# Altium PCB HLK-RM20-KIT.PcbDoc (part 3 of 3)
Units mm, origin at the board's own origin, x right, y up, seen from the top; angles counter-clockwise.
Board outline 152 x 109 mm, 2 copper layers (Top Layer, Bottom Layer), stack 0.325 mm thick; 212 components, 285 nets, 988 pads, 747 vias.
Unrouted connection lines stored in the file: 195.
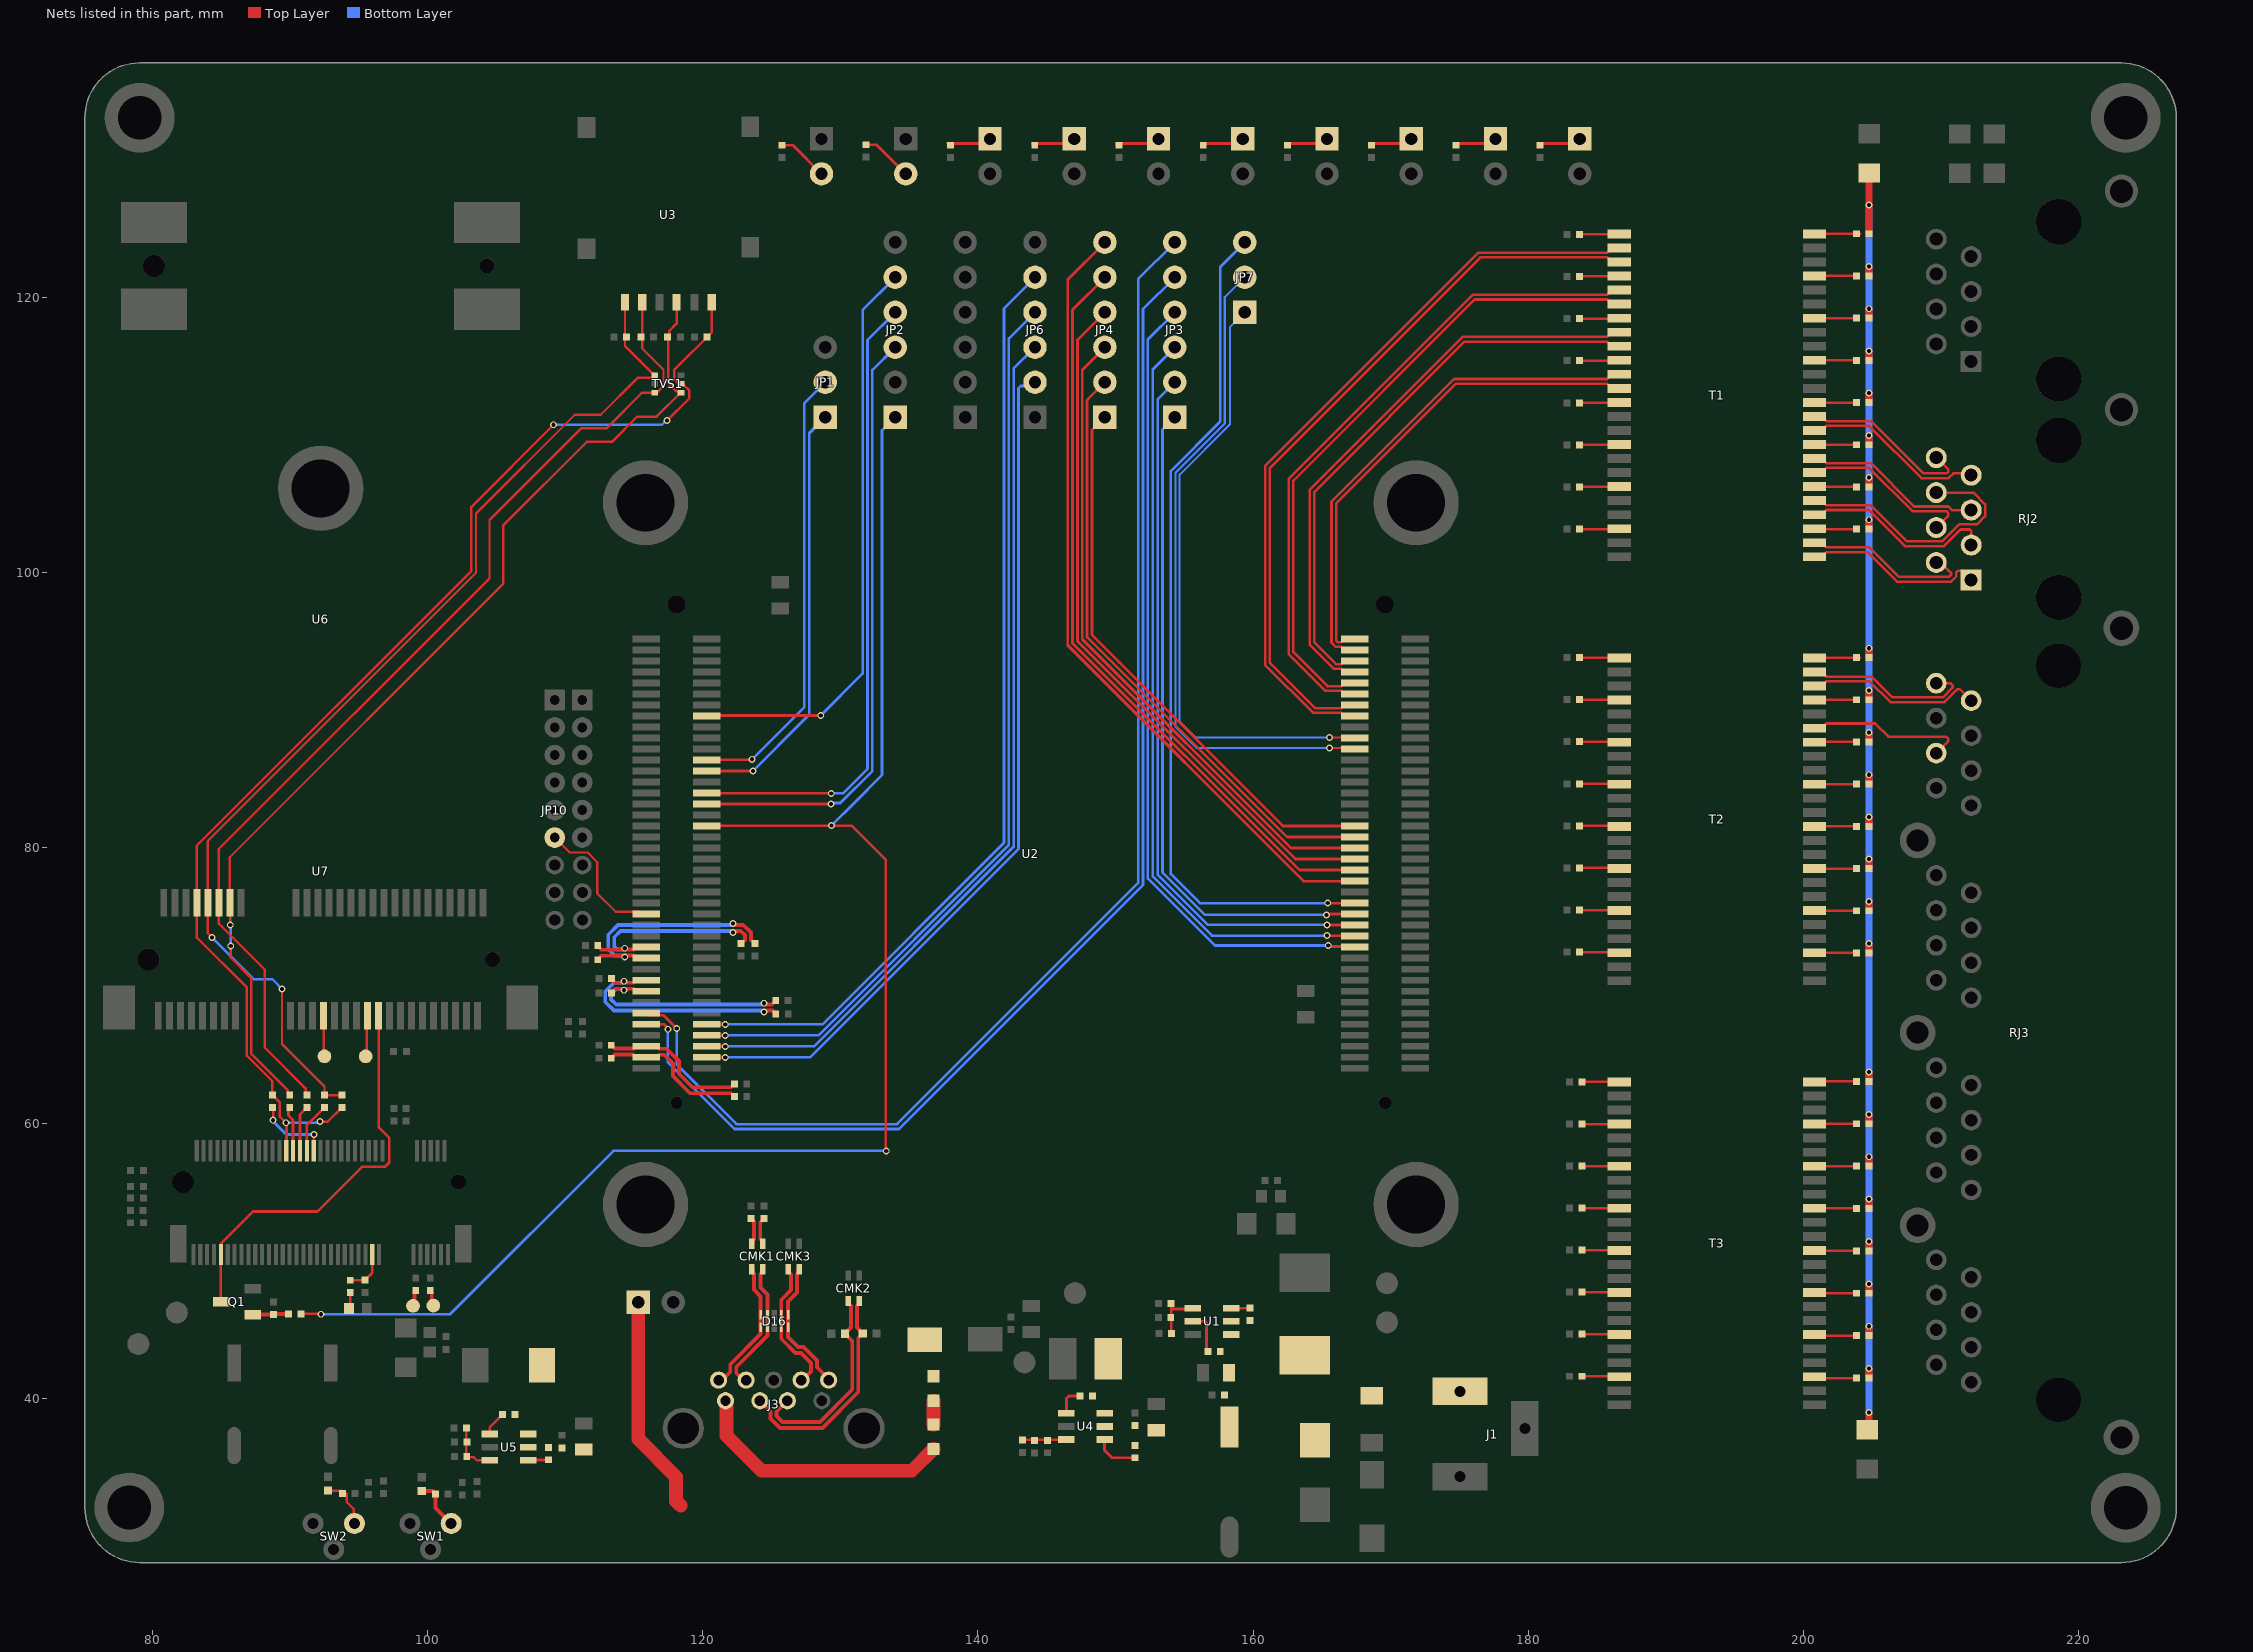
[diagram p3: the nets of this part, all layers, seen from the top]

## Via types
v1: diameter 0.5, hole 0.3, Top Layer to Bottom Layer, tented both sides, 747 vias

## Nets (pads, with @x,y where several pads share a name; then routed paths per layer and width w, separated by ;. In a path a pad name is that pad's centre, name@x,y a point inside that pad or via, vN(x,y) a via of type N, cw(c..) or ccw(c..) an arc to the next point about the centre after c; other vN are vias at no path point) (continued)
MTXV_P4_C_P: RJ3.D4 T2.43 | length 11.7
  Top Layer w0.188: T2.43@200.794,88.7 201.324,88.7 201.55,88.926 201.55,88.93 201.66,89.04 205.204,89.04 206.154,88.09 210.364,88.09 210.526,87.929 210.526,87.773 RJ3.D4@209.64,86.887
MTXV_P4_D_N: RJ3.D8 T2.47 | length 12.5
  Top Layer w0.188: T2.47@200.794,92.78 201.324,92.78 201.55,92.554 201.55,92.551 201.66,92.441 204.938,92.441 206.444,90.935 210.116,90.935 210.829,91.648 210.829,91.804 210.665,91.967 RJ3.D8@209.64,91.967
MTXV_P4_D_P: RJ3.D7 T2.46 | length 12.9
  Top Layer w0.188: T2.46@200.794,91.76 201.324,91.76 201.55,91.986 201.55,91.99 201.66,92.1 204.797,92.1 206.303,90.595 210.257,90.595 211.192,91.529 211.348,91.529 RJ3.D7@212.18,90.697
MTXV_P5_A_N: RJ2.2 T1.26 | length 12.5
  Top Layer w0.188: T1.26@200.794,102.175 201.324,102.175 201.55,101.949 201.55,101.946 201.66,101.836 204.785,101.836 206.927,99.693 210.577,99.693 210.712,99.829 210.712,99.984 209.959,100.737 RJ2.2@209.64,100.737
MTXV_P5_A_P: RJ2.1 T1.25 | length 13.2
  Top Layer w0.188: T1.25@200.794,101.155 201.324,101.155 201.55,101.381 201.55,101.385 201.66,101.495 204.644,101.495 206.786,99.353 210.718,99.353 211.094,99.728 211.094,100.025 211.204,100.135 211.512,100.135 RJ2.1@212.18,99.467
MTXV_P5_B_N: RJ2.6 T1.29 | length 19.1
  Top Layer w0.188: T1.29@200.794,105.235 201.324,105.235 201.55,105.009 201.55,105.006 201.66,104.896 204.886,104.896 207.513,102.269 210.057,102.269 211.306,103.517 212.593,103.517 213.188,104.113 213.188,104.965 212.336,105.817 RJ2.6@209.64,105.817
MTXV_P5_B_P: RJ2.3 T1.28 | length 14.2
  Top Layer w0.188: T1.28@200.794,104.215 201.324,104.215 201.55,104.441 201.55,104.445 201.66,104.555 204.745,104.555 207.372,101.929 210.198,101.929 211.409,103.139 212.07,103.139 212.18,103.029 RJ2.3@212.18,102.007
MTXV_P5_C_N: RJ2.5 T1.32 | length 12.9
  Top Layer w0.188: T1.32@200.794,108.295 201.324,108.295 201.55,108.069 201.55,108.066 201.66,107.956 204.893,107.956 208.04,104.809 210.517,104.809 210.778,104.547 RJ2.5@212.18,104.547
MTXV_P5_C_P: RJ2.4 T1.31 | length 12.6
  Top Layer w0.188: T1.31@200.794,107.275 201.324,107.275 201.55,107.501 201.55,107.505 201.66,107.615 204.752,107.615 207.899,104.469 210.376,104.469 210.526,104.319 210.526,104.163 RJ2.4@209.64,103.277
MTXV_P5_D_N: RJ2.8 T1.35 | length 12.9
  Top Layer w0.188: T1.35@200.794,111.355 201.324,111.355 201.55,111.129 201.55,111.126 201.66,111.016 204.9,111.016 208.698,107.218 210.403,107.218 210.514,107.328 210.514,107.484 RJ2.8@209.64,108.357
MTXV_P5_D_P: RJ2.7 T1.34 | length 13.3
  Top Layer w0.188: T1.34@200.794,110.335 201.324,110.335 201.55,110.561 201.55,110.565 201.66,110.675 204.759,110.675 208.557,106.877 210.544,106.877 210.89,107.223 212.044,107.223 RJ2.7@212.18,107.087
NetC1_1: C1.1 U1.6 | length 1.3
  Top Layer w0.188: U1.6@158.422,46.543 158.43,46.55 159.743,46.55 C1.1@159.751,46.558
NetC1_2: C1.2 L1.1 U1.5
NetC7_1: C7.1 U5.1 | length 1.8
  Top Layer w0.178: U5.1@104.53,37.393 104.53,37.904 C7.1@105.442,38.816
NetC7_2: C7.2 L2.1 U5.6
NetC8_1: C8.1 R2.2 R5.1 U1.1 | length 3.8
  Top Layer w0.2: C8.1@154.043,46.888 154.046,46.886 154.046,46.488 ; R5.1@154.049,44.706 154.046,44.709 154.046,46.488 ; U1.1@155.622,46.543 155.567,46.488 154.046,46.488
NetC15_1: C15.1 U4.1 | length 2.1
  Top Layer w0.2: U4.1@146.429,38.91 146.429,39.997 146.602,40.17 C15.1@147.4,40.17
NetC15_2: C15.2 L4.1 U4.6
NetC20_1: C20.1 R6.2 R7.1 U5.3 | length 3.9
  Top Layer w0.178: R7.1@102.818,35.781 R6.2@102.818,37.85 ; R7.1@102.845,35.781 102.919,35.708 103.362,35.708 103.576,35.493 U5.3@104.53,35.493
NetC23_1: C23.1 R10.2 R12.1 U4.3 | length 3.2
  Top Layer w0.2: C23.1@143.23,36.961 143.255,36.985 146.405,36.985 U4.3@146.429,37.01
NetC32_1: C32.1 CMK1.2 | length 2
  Top Layer w0.283: C32.1@123.501,53.072 123.713,52.86 123.713,51.574 123.6,51.462 123.6,51.287 CMK1.2@123.541,51.229
NetC33_1: C33.1 CMK1.1 | length 2
  Top Layer w0.283: CMK1.1@124.341,51.229 124.341,51.404 124.174,51.57 124.174,52.788 C33.1@124.458,53.072
NetC34_1: C34.1 C60.1 R38.1 R39.1 R40.1 R41.1 R42.1 R43.1 R45.1 R46.1 R47.1 R48.1 R49.1 R50.1 R51.1 R52.1 R53.1 R54.1 R55.1 R56.1 R57.1 R58.1 R59.1 R60.1 R61.1 R62.1 | length 109.1
  Top Layer w0.5: C60.1@204.62,37.712 204.747,37.839 v1(204.747,38.953) ; R38.1@204.747,124.68 v1(204.747,126.71) 204.747,129.019 C34.1@204.772,129.044 ; R62.1@204.751,41.472 v1@204.751,42.156 ; R61.1@204.751,44.552 v1@204.751,45.235 ; R60.1@204.751,47.632 v1@204.751,48.315 ; R59.1@204.751,50.712 v1@204.751,51.395 ; R58.1@204.751,53.792 v1@204.751,54.475 ; R57.1@204.751,56.872 v1@204.751,57.555 ; R56.1@204.751,59.952 v1@204.751,60.635 ; R55.1@204.751,63.032 v1@204.751,63.715 ; R54.1@204.751,72.369 v1@204.751,73.052 ; R53.1@204.751,75.435 v1@204.751,76.118 ; R52.1@204.751,78.5 v1@204.751,79.183 ; R51.1@204.751,81.565 v1@204.751,82.249 ; R50.1@204.751,84.631 v1@204.751,85.314 ; R49.1@204.751,87.696 v1@204.751,88.38 ; R48.1@204.751,90.762 v1@204.751,91.445 ; R47.1@204.751,93.827 v1@204.751,94.51 ; R46.1@204.751,103.165 v1@204.751,103.848 ; R45.1@204.751,106.232 v1@204.751,106.915 ; R43.1@204.751,109.299 v1@204.751,109.982 ; R42.1@204.751,112.366 v1@204.751,113.049 ; R41.1@204.751,115.432 v1@204.751,116.116 ; R40.1@204.751,118.499 v1@204.751,119.183 ; R39.1@204.751,121.566 v1@204.751,122.249
  Bottom Layer w0.5: v1(204.747,38.953) v1(204.747,42.154) 204.751,42.157 204.751,48.314 204.751,60.633 204.751,73.05 204.751,79.181 204.751,91.443 204.751,116.114 204.751,119.181 204.751,126.706 v1(204.747,126.71)
  other v1: 204.747,45.234 204.747,48.314 204.747,51.394 204.747,54.473 204.747,57.553 204.747,60.633 204.747,63.713 204.747,73.05 204.747,76.116 204.747,79.181 204.747,82.247 204.747,85.312 204.747,88.378 204.747,91.443 204.747,94.509 204.747,103.846 204.747,106.913 204.747,109.98 204.747,113.047 204.747,116.114 204.747,119.181 204.747,122.248
NetC35_2: C35.2 T1.1 | length 2.9
  Top Layer w0.181: C35.2@183.716,124.588 T1.1@186.566,124.588
NetC36_2: C36.2 T1.4 | length 2.9
  Top Layer w0.181: C36.2@183.716,121.528 186.566,121.528 T1.4@186.594,121.555
NetC37_2: C37.2 T1.7 | length 2.9
  Top Layer w0.181: C37.2@183.716,118.468 186.567,118.468 T1.7@186.594,118.495
NetC38_2: C38.2 T1.10 | length 2.9
  Top Layer w0.181: C38.2@183.716,115.408 186.567,115.408 T1.10@186.594,115.435
NetC39_2: C39.2 T1.13 | length 2.9
  Top Layer w0.181: C39.2@183.716,112.348 186.567,112.348 T1.13@186.594,112.375
NetC41_2: C41.2 T1.16 | length 2.9
  Top Layer w0.181: C41.2@183.716,109.288 186.567,109.288 T1.16@186.594,109.315
NetC42_2: C42.2 T1.19 | length 2.9
  Top Layer w0.181: C42.2@183.716,106.229 186.567,106.229 T1.19@186.594,106.255
NetC43_2: C43.2 T1.22 | length 2.9
  Top Layer w0.181: C43.2@183.716,103.169 186.567,103.169 T1.22@186.594,103.195
NetC44_2: C44.2 T2.1 | length 2.9
  Top Layer w0.181: C44.2@183.716,93.831 186.563,93.831 T2.1@186.594,93.8
NetC45_2: C45.2 T2.4 | length 2.9
  Top Layer w0.181: C45.2@183.716,90.773 186.561,90.773 T2.4@186.594,90.74
NetC46_2: C46.2 T2.7 | length 2.9
  Top Layer w0.181: C46.2@183.716,87.715 186.56,87.715 T2.7@186.594,87.68
NetC47_2: C47.2 T2.10 | length 2.9
  Top Layer w0.181: C47.2@183.716,84.656 186.558,84.656 T2.10@186.594,84.62
NetC48_2: C48.2 T2.13 | length 2.9
  Top Layer w0.181: C48.2@183.716,81.598 186.556,81.598 T2.13@186.594,81.56
NetC49_2: C49.2 T2.16 | length 2.9
  Top Layer w0.181: C49.2@183.716,78.54 186.555,78.54 T2.16@186.594,78.5
NetC50_2: C50.2 T2.19 | length 2.9
  Top Layer w0.181: C50.2@183.716,75.481 186.553,75.481 T2.19@186.594,75.44
NetC51_2: C51.2 T2.22 | length 2.9
  Top Layer w0.181: C51.2@183.716,72.423 186.551,72.423 T2.22@186.594,72.38
NetC52_2: C52.2 T3.1 | length 2.7
  Top Layer w0.181: C52.2@183.885,62.987 T3.1@186.594,62.985 T3.1@186.594,62.985
NetC53_2: C53.2 T3.4 | length 2.7
  Top Layer w0.181: C53.2@183.885,59.931 186.588,59.931 T3.4@186.594,59.925
NetC54_2: C54.2 T3.7 | length 2.7
  Top Layer w0.181: C54.2@183.885,56.876 186.583,56.876 T3.7@186.594,56.865
NetC55_2: C55.2 T3.10 | length 2.7
  Top Layer w0.181: C55.2@183.885,53.821 186.578,53.821 T3.10@186.594,53.805
NetC56_2: C56.2 T3.13 | length 2.7
  Top Layer w0.181: C56.2@183.885,50.766 186.573,50.766 T3.13@186.594,50.745
NetC57_2: C57.2 T3.16 | length 2.7
  Top Layer w0.181: C57.2@183.885,47.711 186.569,47.711 T3.16@186.594,47.685
NetC58_2: C58.2 T3.19 | length 2.7
  Top Layer w0.181: C58.2@183.885,44.656 186.564,44.656 T3.19@186.594,44.625
NetC59_2: C59.2 T3.22 | length 2.7
  Top Layer w0.181: C59.2@183.885,41.601 186.559,41.601 T3.22@186.594,41.565
NetCMK1_3: CMK1.3 D16.5 D16.6 J3.9 | length 9.8
  Top Layer w0.283: J3.9@121.148,41.32 121.41,41.32 121.993,41.903 121.993,42.454 124.203,44.664 D16.6@124.203,45.163 D16.5@124.203,46.063 124.203,47.411 123.709,47.905 123.709,49.035 123.6,49.145 123.6,49.32 CMK1.3@123.541,49.378
NetCMK1_4: CMK1.4 D16.4 D16.7 J3.8 | length 9.7
  Top Layer w0.283: J3.8@123.148,41.32 122.96,41.32 122.429,41.851 122.429,42.274 124.703,44.548 D16.7@124.703,45.163 D16.4@124.703,46.063 124.703,47.527 124.187,48.043 124.187,49.05 124.341,49.204 CMK1.4@124.341,49.378
NetCMK2_1: CMK2.1 D17.2 J3.3 | length 15
  Top Layer w0.283: J3.3@126.148,39.82 125.349,39.02 125.349,38.722 125.791,38.28 128.514,38.28 130.864,40.63 130.864,44.157 D17.2@130.326,44.695 130.761,45.13 130.761,46.693 130.621,46.834 130.621,47.009 CMK2.1@130.563,47.067
NetCMK2_2: CMK2.2 D18.2 J3.2 | length 16.3
  Top Layer w0.283: J3.2@124.148,39.82 124.913,39.055 124.913,38.541 125.61,37.844 128.695,37.844 131.3,40.449 131.3,44.39 D18.2@131.619,44.709 131.197,45.131 131.197,46.727 131.362,46.892 CMK2.2@131.362,47.067
NetCMK3_3: CMK3.3 D16.2 D16.9 J3.6 | length 9.9
  Top Layer w0.283: CMK3.3@126.219,49.378 126.277,49.32 126.277,49.145 126.42,49.002 126.42,47.87 125.703,47.152 D16.2@125.703,46.063 D16.9@125.703,45.163 125.703,44.329 126.743,43.289 127.129,43.289 127.859,42.558 127.859,41.943 127.237,41.32 J3.6@127.148,41.32
NetCMK3_4: CMK3.4 D16.1 D16.10 J3.5 | length 9.8
  Top Layer w0.283: CMK3.4@127.019,49.378 126.96,49.32 126.96,49.145 126.856,49.041 126.856,47.689 126.203,47.036 D16.1@126.203,46.063 D16.10@126.203,45.163 126.203,44.445 126.924,43.725 127.309,43.725 128.295,42.739 128.295,42.252 129.148,41.399 J3.5@129.148,41.32
NetD4_1: D4.1 R13.1 | length 3
  Top Layer w0.2: R13.1@180.852,131.188 183.427,131.188 D4.1@183.729,131.489
NetD5_1: D5.1 R17.1 | length 3.2
  Top Layer w0.2: R17.1@174.699,131.188 177.501,131.188 D5.1@177.803,131.489
NetD6_1: D6.1 R20.1 | length 3.2
  Top Layer w0.2: R20.1@168.546,131.188 171.337,131.188 D6.1@171.638,131.489
NetD7_2: D7.2 R19.1 SW1.2 | length 3.7
  Top Layer w0.3: D7.2@99.569,33.259 100.37,33.259 R19.1@100.586,33.043 100.586,32.036 SW1.2@101.716,30.906
NetD8_1: D8.1 R23.1 | length 3.2
  Top Layer w0.2: R23.1@162.393,131.188 165.172,131.188 D8.1@165.473,131.489
NetD9_1: D9.1 R26.1 | length 3.1
  Top Layer w0.2: R26.1@156.24,131.188 158.939,131.188 D9.1@159.24,131.489
NetD10_1: D10.1 R31.1 | length 3.1
  Top Layer w0.2: R31.1@150.087,131.188 152.774,131.188 D10.1@153.076,131.489
NetD11_1: D11.1 R34.1 | length 3.1
  Top Layer w0.2: R34.1@143.934,131.188 146.61,131.188 D11.1@146.911,131.489
NetD12_2: D12.2 R30.1 SW2.2 | length 3.6
  Top Layer w0.178: D12.2@92.755,33.289 93.721,33.289 93.721,33.178 R30.1@93.825,33.074 ; 94.129,33.07 94.129,32.445 94.64,31.934 94.64,30.945 SW2.2@94.679,30.906
NetD13_1: D13.1 R35.1 | length 3.1
  Top Layer w0.2: R35.1@137.781,131.188 140.445,131.188 D13.1@140.747,131.489
NetD14_2: D14.2 R8.1 | length 3.7
  Top Layer w0.2: R8.1@125.759,131.063 126.544,131.063 D14.2@128.626,128.981
NetD19_2: D19.2 R27.1 | length 1.2
  Top Layer w0.2: D19.2@94.284,46.517 94.382,46.615 R27.1@94.382,47.673
NetD20_2: D20.2 R32.2 | length 3.8
  Top Layer w0.2: R32.2@131.873,131.101 132.628,131.101 D20.2@134.748,128.981
NetF1_1: F1.1 J3.1 | length 19.3
  Top Layer w1: J3.1@121.648,39.82 121.696,39.772 121.696,39.595 121.722,39.569 121.722,37.278 124.265,34.735 135.185,34.735 F1.1@136.772,36.322
NetF1_2: F1.2 FB1.2 | length 1.7
  Top Layer w1: F1.2@136.772,38.1 FB1.2@136.772,39.827
NetF2_1: F2.1 J1.1
NetQ1_1: Q1.1 R11.1 R14.2 | length 2.6
  Top Layer w0.283: Q1.1@87.277,46.067 87.287,46.077 88.798,46.077 R14.2@88.808,46.087 88.832,46.111 89.864,46.111 R11.1@89.888,46.134
NetR1_2: R1.2 U1.2 | length 3.1
  Top Layer w0.188: U1.2@155.622,45.593 156.495,45.593 156.605,45.483 R1.2@156.605,43.383
NetR4_2: R4.2 U5.4 | length 1.5
  Top Layer w0.2: U5.4@107.33,35.493 107.348,35.511 108.757,35.511 R4.2@108.775,35.529
NetR9_2: R9.2 U4.4 | length 3.2
  Top Layer w0.2: U4.4@149.229,37.01 149.191,36.972 149.191,36.221 149.733,35.679 R9.2@151.407,35.679
NetR21_2: R21.2 U7.46 | length 3
  Top Layer w0.2: R21.2@89.897,61.134 89.897,60.549 90.225,60.221 U7.46@90.225,58.229
NetR22_2: R22.2 U7.44 | length 3.3
  Top Layer w0.2: U7.44@90.725,58 90.725,60.614 R22.2@91.244,61.134
NetR24_2: R24.2 U7.42 | length 5.5
  Top Layer w0.2: 92.021,60.65 91.225,59.853 ; 92.022,60.65 R24.2@92.506,61.134 ; 91.225,59.853 U7.42@91.225,58 91.225,59.853
NetR33_1: R33.1 TP3.1 | length 1.2
  Top Layer w0.283: TP3.1@98.944,46.716 99.041,46.813 99.041,47.733 R33.1@99.138,47.83
NetR37_1: R37.1 TP5.1 | length 1.2
  Top Layer w0.283: R37.1@100.196,47.83 100.304,47.721 100.304,46.85 TP5.1@100.418,46.737
NetR38_2: R38.2 T1.48 | length 3.3
  Top Layer w0.181: T1.48@200.794,124.615 204.098,124.615 204.12,124.637
NetR39_2: R39.2 T1.45 | length 3.1
  Top Layer w0.181: T1.45@200.794,121.555 200.805,121.566 R39.2@203.851,121.566
NetR40_2: R40.2 T1.42 | length 3.1
  Top Layer w0.181: T1.42@200.794,118.495 200.798,118.499 R40.2@203.851,118.499
NetR41_2: R41.2 T1.39 | length 3.1
  Top Layer w0.181: T1.39@200.794,115.435 200.797,115.432 R41.2@203.851,115.432
NetR42_2: R42.2 T1.36 | length 3.1
  Top Layer w0.181: T1.36@200.794,112.375 200.804,112.366 R42.2@203.851,112.366
NetR43_2: R43.2 T1.33 | length 3.1
  Top Layer w0.181: T1.33@200.794,109.315 200.811,109.299 R43.2@203.851,109.299
NetR45_2: R45.2 T1.30 | length 3.1
  Top Layer w0.181: T1.30@200.794,106.255 200.818,106.232 R45.2@203.851,106.232
NetR46_2: R46.2 T1.27 | length 3.1
  Top Layer w0.181: T1.27@200.794,103.195 200.825,103.165 R46.2@203.851,103.165
NetR47_2: R47.2 T2.48 | length 3.3
  Top Layer w0.181: T2.48@200.794,93.8 200.821,93.827 203.824,93.827 203.851,93.8 R47.2@204.098,93.8
NetR48_2: R48.2 T2.45 | length 3.1
  Top Layer w0.181: T2.45@200.794,90.74 200.815,90.762 R48.2@203.851,90.762
NetR49_2: R49.2 T2.42 | length 3.1
  Top Layer w0.181: T2.42@200.794,87.68 200.81,87.696 203.839,87.696 R49.2@203.851,87.684
NetR50_2: R50.2 T2.39 | length 3.1
  Top Layer w0.181: T2.39@200.794,84.62 200.805,84.631 R50.2@203.851,84.631
NetR51_2: R51.2 T2.36 | length 3.1
  Top Layer w0.181: T2.36@200.794,81.56 200.799,81.565 203.836,81.565 R51.2@203.851,81.55
NetR52_2: R52.2 T2.33 | length 6.1
  Top Layer w0.181: T2.33@200.794,78.5 R52.2@203.851,78.5 ; T2.33@200.811,78.483 R52.2@203.851,78.483
NetR53_2: R53.2 T2.30 | length 3.1
  Top Layer w0.181: T2.30@200.794,75.44 200.8,75.435 203.833,75.435 R53.2@203.851,75.417
NetR54_2: R54.2 T2.27 | length 3.1
  Top Layer w0.181: T2.27@200.794,72.38 200.805,72.369 R54.2@203.851,72.369
NetR55_2: R55.2 T3.48 | length 3.1
  Top Layer w0.181: T3.48@200.794,62.985 200.841,63.032 R55.2@203.851,63.032
NetR56_2: R56.2 T3.45 | length 3.1
  Top Layer w0.181: T3.45@200.794,59.925 200.821,59.952 R56.2@203.851,59.952
NetR57_2: R57.2 T3.42 | length 3.1
  Top Layer w0.181: T3.42@200.794,56.865 200.801,56.872 R57.2@203.851,56.872
NetR58_2: R58.2 T3.39 | length 3.1
  Top Layer w0.181: T3.39@200.794,53.805 200.807,53.792 R58.2@203.851,53.792
NetR59_2: R59.2 T3.36 | length 3.1
  Top Layer w0.181: T3.36@200.794,50.745 200.827,50.712 R59.2@203.851,50.712
NetR60_2: R60.2 T3.33 | length 3.1
  Top Layer w0.181: T3.33@200.794,47.685 200.847,47.632 R60.2@203.851,47.632
NetR61_2: R61.2 T3.30 | length 3.1
  Top Layer w0.181: T3.30@200.794,44.625 200.867,44.552 R61.2@203.851,44.552
NetR62_2: R62.2 T3.27 | length 3.1
  Top Layer w0.181: T3.27@200.794,41.565 200.887,41.472 R62.2@203.851,41.472
P0_A_TXV_N: T1.11 U2.A77 | length 36.9
  Top Layer w0.188: U2.A77@167.386,94.383 166.636,94.383 166.406,94.613 165.999,94.613 165.689,94.922 165.689,105.17 174.594,114.076 185.728,114.076 185.838,114.186 185.838,114.189 186.064,114.415 T1.11@186.594,114.415
P0_A_TXV_P: T1.12 U2.A79 | length 35.8
  Top Layer w0.188: U2.A79@167.386,95.183 166.636,95.183 166.406,94.953 166.14,94.953 166.029,95.063 166.029,105.029 174.735,113.735 185.728,113.735 185.838,113.625 185.838,113.621 186.064,113.395 T1.12@186.594,113.395
P0_B_TXV_N: T1.8 U2.A73 | length 42.6
  Top Layer w0.188: U2.A73@167.386,92.783 166.636,92.783 166.406,93.013 165.876,93.013 164.099,94.79 164.099,106.008 175.227,117.136 185.728,117.136 185.838,117.246 185.838,117.249 186.064,117.475 T1.8@186.594,117.475
P0_B_TXV_P: T1.9 U2.A75 | length 41.4
  Top Layer w0.188: U2.A75@167.386,93.583 166.636,93.583 166.406,93.353 166.017,93.353 164.44,94.931 164.44,105.867 175.368,116.795 185.728,116.795 185.838,116.685 185.838,116.681 185.938,116.582 T1.9@186.609,116.582
P0_C_TXV_N: T1.5 U2.A69 | length 48.4
  Top Layer w0.188: U2.A69@167.386,91.183 166.636,91.183 166.406,91.413 165.255,91.413 162.575,94.093 162.575,106.821 175.95,120.196 185.728,120.196 185.838,120.306 185.838,120.309 186.064,120.535 T1.5@186.594,120.535
P0_C_TXV_P: T1.6 U2.A71 | length 47.3
  Top Layer w0.188: U2.A71@167.386,91.983 166.636,91.983 166.406,91.753 165.396,91.753 162.916,94.234 162.916,106.68 176.091,119.855 185.728,119.855 185.838,119.745 185.838,119.741 186.064,119.515 T1.6@186.594,119.515
P0_D_TXV_N: T1.2 U2.A65 | length 54.8
  Top Layer w0.188: U2.A65@167.386,89.583 166.636,89.583 166.406,89.813 164.366,89.813 160.873,93.306 160.873,107.761 176.368,123.256 185.728,123.256 185.838,123.366 185.838,123.369 186.064,123.595 T1.2@186.594,123.595
P0_D_TXV_P: T1.3 U2.A67 | length 53.7
  Top Layer w0.188: U2.A67@167.386,90.383 166.636,90.383 166.406,90.153 164.507,90.153 161.214,93.447 161.214,107.62 176.509,122.915 185.728,122.915 185.838,122.805 185.838,122.801 186.064,122.575 T1.3@186.594,122.575
PCIE_CK_N: JP3.5 U2.B9 | length 93.2
  Top Layer w0.2: U2.B9@115.886,67.183 117.186,67.183 117.403,66.966 117.403,66.875 v1(117.46,66.817)
  Bottom Layer w0.2: v1(117.46,66.817) 117.46,64.413 122.307,59.566 134.258,59.566 151.993,77.301 151.993,119.15 JP3.5@154.305,121.463
PCIE_CK_P: JP3.6 U2.B11 | length 95.5
  Top Layer w0.2: U2.B11@115.886,67.983 116.036,67.833 117.155,67.833 v1(118.11,66.878)
  Bottom Layer w0.2: v1(118.11,66.878) 118.11,64.262 122.453,59.919 134.112,59.919 151.64,77.447 151.64,121.338 JP3.6@154.305,124.003
PCIE_PERESET_N: JP10.6 U2.B29 | length 9.9
  Top Layer w0.16: JP10.6@109.241,80.75 110.333,79.657 111.639,79.657 112.336,78.96 112.336,76.691 113.674,75.353 115.341,75.353 U2.B29@115.511,75.183
PERST#: Q1.3 U6.33 U7.67 | length 29.9
  Top Layer w0.2: Q1.3@84.991,47.017 84.975,47.033 U7.67@84.975,50.45 85.025,50.5 85.025,51.282 87.312,53.569 91.986,53.569 95.237,56.82 96.888,56.82 97.218,57.15 97.218,58.903 96.456,59.665 96.456,67.769 U6.33@96.425,67.8
PERST_4G: JP2.1 R11.2 U2.B46 | length 114.3
  Top Layer w0.2: R11.2@90.788,46.134 92.223,46.134 v1(92.25,46.108) ; U2.B46@120.286,81.583 120.319,81.617 v1(129.353,81.617) 130.813,81.617 133.305,79.125 133.305,58.007 v1(133.329,57.983)
  Bottom Layer w0.2: v1(92.25,46.108) 101.632,46.108 113.507,57.983 v1(133.329,57.983) ; v1(129.353,81.617) 130.98,83.244 130.98,83.245 133.027,85.292 133.027,110.345 JP2.1@133.985,111.303
PWM0: JP2.5 U2.B66 | length 42.4
  Top Layer w0.2: U2.B66@120.286,89.583 120.322,89.619 v1(128.57,89.619)
  Bottom Layer w0.2: v1(128.57,89.619) 131.618,92.667 131.618,119.095 JP2.5@133.985,121.463
SIM2_CLK: C12.1 R22.1 TVS1.3 U3.4 U6.12 | length 75.9
  Top Layer w0.178: R22.1@91.244,62.034 91.135,62.143 91.135,62.518 88.176,65.477 88.176,71.139 84.825,74.49 U6.12@84.825,76 84.825,79.908 104.5,99.583 104.5,103.835 111.155,110.49 112.991,110.49 115.565,113.064 TVS1.3@116.508,113.064 ; U3.4@115.596,119.65 115.596,116.292 117.143,114.745 117.143,113.558 TVS1.3@116.604,113.018
SIM2_DATA: C13.1 R3.1 R24.1 TVS1.1 U3.3 U6.10 | length 79.2
  Top Layer w0.178: v1(84.34,73.482) 84.34,73.495 84.025,73.81 U6.10@84.025,76 84.025,80.498 103.517,99.99 103.517,104.292 110.698,111.473 112.584,111.473 115.267,114.155 116.249,114.155 TVS1.1@116.458,114.364 ; v1(89.42,69.748) 89.42,65.735 92.506,62.65 R24.1@92.506,62.034 R3.1@93.768,62.034 ; U3.3@114.346,119.65 114.346,117.145 114.346,116.476 TVS1.1@116.458,114.364 ; TVS1.1@116.508,114.364 TVS1.1@116.458,114.364
  Bottom Layer w0.178: v1(84.34,73.482) 87.363,70.46 88.709,70.46 v1(89.42,69.748)
SIM2_DET: R25.2 U7.40 | length 5.5
  Top Layer w0.2: v1(88.761,60.21) 88.786,60.234 R25.2@88.786,61.134 ; U7.40@91.729,58.004 91.729,59.164 v1(91.733,59.168)
  Bottom Layer w0.2: v1(88.761,60.21) 88.761,60.134 89.726,59.168 v1(91.733,59.168)
SIM2_RST: C11.1 R21.1 TVS1.4 U3.5 U6.14 | length 75.6
  Top Layer w0.178: v1(85.662,74.395) 85.662,75.963 U6.14@85.625,76 85.625,79.318 105.483,99.176 105.483,103.428 111.562,109.507 113.398,109.507 115.233,111.343 116.637,111.343 TVS1.4@118.358,113.064 ; v1(85.691,72.864) 85.691,72.02 87.193,70.518 87.193,65.031 89.826,62.399 89.826,62.19 R21.1@89.982,62.034 ; U3.5@118.096,119.65 118.096,118.096 117.561,117.561 117.561,117.233 117.474,117.145 117.474,113.801 118.1,113.175 118.247,113.175 TVS1.4@118.358,113.064 ; TVS1.4@118.408,113.064 TVS1.4@118.358,113.064
  Bottom Layer w0.178: v1(85.662,74.395) 85.691,74.365 v1(85.691,72.864)
SIM2_VDD: C27.2 R3.2 R25.1 TVS1.5 U3.6 U6.8 U7.48 | length 90.1
  Top Layer w0.178: v1(89.705,60.021) 89.262,60.463 89.262,61.492 R25.1@88.721,62.034 88.721,63.037 86.863,64.895 86.863,69.842 83.225,73.48 U6.8@83.225,76 83.225,80.165 103.187,100.127 103.187,104.777 v1(109.159,110.749) ; v1(92.19,60.108) 92.742,60.108 R3.2@93.768,61.134 ; v1(117.399,111.049) 119.024,112.674 119.024,113.239 118.612,113.651 118.329,113.651 117.917,114.064 117.917,114.728 120.646,117.458 U3.6@120.646,119.65
  Top Layer w0.2: v1(89.705,60.021) 89.738,59.987 U7.48@89.738,58.013
  Bottom Layer w0.178: v1(89.705,60.021) 92.103,60.021 v1(92.19,60.108) ; v1(109.159,110.749) 117.029,110.749 117.328,111.049 v1(117.399,111.049)
SMI_MDC: JP7.1 U2.A61 | length 44.9
  Top Layer w0.152: v1(165.532,88.011) 167.358,88.011 U2.A61@167.386,87.983
  Bottom Layer w0.152: JP7.1@159.385,118.923 158.301,117.839 158.301,110.771 154.65,107.12 154.65,89.179 155.819,88.011 v1(165.532,88.011)
SMI_MDIO: JP7.2 U2.A59 | length 48.5
  Top Layer w0.152: v1(165.532,87.249) 167.32,87.249 U2.A59@167.386,87.183
  Bottom Layer w0.152: JP7.2@159.385,121.463 157.936,120.013 157.936,110.836 154.346,107.246 154.346,88.798 155.895,87.249 v1(165.532,87.249)
SPI1_CLK: JP2.3 U2.B50 | length 44.5
  Top Layer w0.2: U2.B50@120.286,83.183 120.3,83.197 v1(129.325,83.197)
  Bottom Layer w0.2: v1(129.325,83.197) 129.382,83.254 129.992,83.254 132.322,85.584 132.322,114.72 JP2.3@133.985,116.383
SPI1_CS: JP2.4 U2.B52 | length 46.5
  Top Layer w0.2: U2.B52@120.286,83.983 120.322,83.947 120.338,83.963 v1(129.335,83.963)
  Bottom Layer w0.2: v1(129.335,83.963) 130.203,83.963 131.97,85.73 131.97,116.908 JP2.4@133.985,118.923
SPI2_CLK: JP4.5 U2.A37 | length 54.9
  Top Layer w0.2: JP4.5@149.225,121.463 146.872,119.11 146.872,94.873 163.362,78.383 U2.A37@167.386,78.383
SPI2_CS: JP4.1 U2.A45 | length 41.1
  Top Layer w0.2: JP4.1@149.225,111.303 148.282,110.36 148.282,95.479 150.279,93.482 150.279,93.459 162.155,81.583 U2.A45@167.386,81.583
SPI2_HOLD: JP4.3 U2.A41 | length 48
  Top Layer w0.2: JP4.3@149.225,116.383 147.577,114.735 147.577,95.164 162.758,79.983 U2.A41@167.386,79.983
SPI2_MISO: JP4.6 U2.A35 | length 58.4
  Top Layer w0.2: JP4.6@149.225,124.003 146.52,121.298 146.52,94.727 163.663,77.583 U2.A35@167.386,77.583
SPI2_MOSI: JP4.2 U2.A43 | length 44.5
  Top Layer w0.2: JP4.2@149.225,113.843 147.93,112.547 147.93,95.31 149.192,94.048 162.457,80.783 U2.A43@167.386,80.783
SPI2_WP: JP4.4 U2.A39 | length 51.5
  Top Layer w0.2: JP4.4@149.225,118.923 147.225,116.923 147.225,95.018 163.06,79.183 U2.A39@167.386,79.183
SS_RX_N: R64.2 R71.2 U2.B15 | length 16.6
  Top Layer w0.283: R64.2@113.351,69.466 113.46,69.574 113.46,69.597 113.626,69.762 114.4,69.762 114.403,69.766 114.954,69.766 115.136,69.583 U2.B15@115.886,69.583 ; v1(124.437,68.712) 124.496,68.712 124.604,68.603 124.994,68.603 125.196,68.805 125.196,68.806 R71.2@125.305,68.915
  Bottom Layer w0.283: v1(114.285,69.657) 114.226,69.657 114.117,69.766 113.728,69.766 113.342,69.38 113.342,68.974 113.713,68.603 124.27,68.603 124.378,68.712 v1(124.437,68.712)
SS_RX_P: R65.2 R70.2 U2.B17 | length 17.8
  Top Layer w0.283: R65.2@113.351,70.495 113.46,70.386 113.46,70.364 113.626,70.198 v1@114.219,70.198 ; v1@114.439,70.201 114.954,70.201 115.136,70.383 U2.B17@115.886,70.383 ; v1(124.437,68.059) 124.496,68.059 124.604,68.168 125.066,68.168 R70.2@125.306,67.928
  Bottom Layer w0.283: v1(114.285,70.309) 114.226,70.309 114.117,70.201 113.547,70.201 112.907,69.561 112.907,68.793 113.533,68.168 124.27,68.168 124.378,68.059 v1(124.437,68.059)
SS_TX_N: R66.2 R69.2 U2.B21 | length 17.7
  Top Layer w0.283: R66.2@112.367,71.868 112.475,71.977 112.475,71.998 112.641,72.164 114.087,72.164 ; v1@114.493,72.165 114.954,72.165 115.136,71.983 U2.B21@115.886,71.983 ; v1(122.199,74.509) 122.258,74.509 122.367,74.4 122.938,74.4 123.501,73.837 123.501,73.311 123.667,73.146 123.687,73.146 R69.2@123.796,73.037
  Bottom Layer w0.283: v1(114.325,72.057) 114.267,72.057 114.158,72.165 113.601,72.165 113.128,72.639 113.128,73.687 113.842,74.4 122.032,74.4 122.141,74.509 v1(122.199,74.509)
SS_TX_P: R67.2 R68.2 U2.B23 | length 16
  Top Layer w0.283: R67.2@112.362,72.895 112.47,72.786 112.47,72.765 112.636,72.599 113.907,72.599 113.908,72.601 114.954,72.601 115.136,72.783 U2.B23@115.886,72.783 ; v1(122.199,73.856) 122.258,73.856 122.367,73.965 122.758,73.965 123.066,73.657 123.066,73.311 122.9,73.146 122.879,73.146 R68.2@122.771,73.037
  Bottom Layer w0.283: v1(114.325,72.709) 114.267,72.709 114.158,72.601 113.781,72.601 113.563,72.819 113.563,73.506 114.022,73.965 122.032,73.965 122.141,73.856 v1(122.199,73.856)
SYS_WATCHDOG: JP7.3 U2.A31 | length 62.4
  Top Layer w0.2: v1(165.417,75.983) U2.A31@167.386,75.983
  Bottom Layer w0.2: JP7.3@159.385,124.003 157.607,122.225 157.607,110.973 154.017,107.383 154.017,78.1 156.134,75.983 v1(165.417,75.983)
SYSRSTB: JP3.1 U2.A29 | length 48.7
  Top Layer w0.2: v1(165.333,75.135) 165.389,75.19 167.379,75.19 U2.A29@167.386,75.183
  Bottom Layer w0.2: JP3.1@154.305,111.303 153.41,110.407 153.41,78.21 156.484,75.135 v1(165.333,75.135)
UART0_RXD: JP1.1 U2.B56 | length 31.2
  Top Layer w0.2: U2.B56@120.286,85.583 120.293,85.591 123.64,85.591 v1(123.647,85.598)
  Bottom Layer w0.2: v1(123.647,85.598) 127.254,89.205 127.733,89.684 127.733,110.131 JP1.1@128.905,111.303
UART0_TXD: JP1.2 U2.B58 | length 32.9
  Top Layer w0.2: U2.B58@120.286,86.383 120.313,86.41 123.545,86.41 v1(123.571,86.436)
  Bottom Layer w0.2: v1(123.571,86.436) 127.381,90.246 127.381,112.319 JP1.2@128.905,113.843
UART_RXD: TP9.1 U6.23 | length 3
  Top Layer w0.178: U6.23@92.425,67.8 92.463,67.762 92.463,64.89 TP9.1@92.502,64.852
UART_TXD: TP8.1 U6.31 | length 3
  Top Layer w0.178: TP8.1@95.502,64.852 95.563,64.913 95.563,67.738 U6.31@95.625,67.8
USB_5V: D3.2 FB1.1
USB_D_N: R18.2 R72.1 U2.B5 | length 11
  Top Layer w0.283: R18.2@113.347,65.66 113.601,65.406 114.959,65.406 115.136,65.583 U2.B5@115.886,65.583 116.636,65.583 116.818,65.401 117.36,65.401 118.257,64.504 118.257,63.587 119.24,62.604 122.053,62.604 R72.1@122.293,62.844
USB_D_P: R15.2 R73.1 U2.B3 | length 11
  Top Layer w0.283: R15.2@113.347,64.711 113.606,64.97 114.949,64.97 115.136,64.783 U2.B3@115.886,64.783 116.636,64.783 116.818,64.965 117.18,64.965 117.821,64.324 117.821,63.407 119.059,62.169 122.053,62.169 R73.1@122.293,61.929
USB_VBUS: JP3.4 U2.A23 | length 59.1
  Top Layer w0.2: v1(165.456,72.898) 165.513,72.841 167.328,72.841 U2.A23@167.386,72.783
  Bottom Layer w0.2: JP3.4@154.305,118.923 152.345,116.963 152.345,77.779 157.226,72.898 v1(165.456,72.898)
VIN: C3.1 C4.2 C5.1 C14.2 C16.1 C18.2 C19.1 D1.2 JP5.1 R1.1 R4.1 R9.1 U1.4 U4.5 U5.5 | length 16.1
  Top Layer w1: JP5.1@115.316,46.99 115.316,37.033 118.059,34.29 118.059,32.537 118.389,32.207
WF2G_LED: JP3.3 U2.A25 | length 55.6
  Top Layer w0.2: v1(165.375,73.619) 167.35,73.619 U2.A25@167.386,73.583
  Bottom Layer w0.2: JP3.3@154.305,116.383 152.705,114.783 152.705,77.918 157.003,73.619 v1(165.375,73.619)
WF5G_LED: JP3.2 U2.A27 | length 52.1
  Top Layer w0.2: v1(165.361,74.405) 165.363,74.403 167.367,74.403 U2.A27@167.386,74.383
  Bottom Layer w0.2: JP3.2@154.305,113.843 153.057,112.595 153.057,78.064 156.716,74.405 v1(165.361,74.405)
WO_JTCK: JP6.4 U2.B8 | length 67.2
  Top Layer w0.283: U2.B8@120.286,66.383 121.628,66.383 v1(121.634,66.377)
  Bottom Layer w0.2: v1(121.634,66.377) 128.394,66.377 142.242,80.225 142.242,117.02 JP6.4@144.145,118.923
WO_JTDI: JP6.5 U2.B10 | length 69.1
  Top Layer w0.283: U2.B10@120.286,67.183 121.628,67.183 v1(121.634,67.177)
  Bottom Layer w0.2: v1(121.634,67.177) 128.696,67.177 141.889,80.371 141.889,119.207 JP6.5@144.145,121.463
WO_JTDO: JP6.2 U2.B4 | length 63.8
  Top Layer w0.283: U2.B4@120.286,64.783 121.628,64.783 v1(121.634,64.777)
  Bottom Layer w0.2: v1(121.634,64.777) 127.791,64.777 142.947,79.933 142.947,113.406 143.112,113.572 143.874,113.572 JP6.2@144.145,113.843
WO_JTMS: JP6.3 U2.B6 | length 65.3
  Top Layer w0.283: U2.B6@120.286,65.583 121.628,65.583 v1(121.634,65.577)
  Bottom Layer w0.2: v1(121.634,65.577) 128.092,65.577 142.594,80.079 142.594,114.832 JP6.3@144.145,116.383
WOWWAN: R27.2 R28.1 U7.23 | length 3.2
  Top Layer w0.2: R27.2@94.382,48.573 94.39,48.581 95.455,48.581 R28.1@95.463,48.589 95.975,49.101 U7.23@95.975,50.45
pads on no net: RJ1. RJ2. RJ3. SW1.0 SW2.0 TVS1.6 U2. U3.2 U6.1 U6.3 U6.5 U6.6 U6.7 U6.11 U6.13 U6.16 U6.17 U6.19 U6.20 U6.22 U6.25 U6.28 U6.30 U6.32 U6.44 U6.45 U6.46 U6.47 U6.48 U6.49 U6.51 U6.53 U6.54 U6.67 U6.68 U7. U7.1 U7.8 U7.20 U7.21 U7.22 U7.24 U7.25 U7.26 U7.28 U7.30 U7.32 U7.34 U7.36 U7.38 U7.41 U7.43 U7.47 U7.49 U7.50 U7.52 U7.53 U7.54 U7.55 U7.56 U7.58 U7.59 U7.60 U7.61 U7.62 U7.63 U7.64 U7.65 U7.66 U7.68 U7.69 U7.75

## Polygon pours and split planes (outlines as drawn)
GND on Top Layer "NONET_L02_P-001" (solid, remove dead copper, pour order 1): 75.089,137.053 75.089,28.058 227.093,28.058 227.093,137.053
GND_EARTH on Top Layer "NONET_L02_P-001" (solid, remove dead copper, pour order 0): 207.536,127.119 207.536,130.69 218.763,130.69 220.312,132.24 220.312,137.04 224.96,137.04 227.221,134.78 227.119,134.678 227.119,127.119
GND on Bottom Layer "NONET_L02_P-001" (solid, remove dead copper, pour order 2): 75.089,137.053 75.089,28.058 227.093,28.058 227.093,137.053

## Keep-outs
Keep-Out Layer:
  lines w0.001: 75.089,32.059 75.089,133.053 ; 79.089,137.053 223.092,137.053 ; 79.09,28.053 223.087,28.053 ; 227.093,32.053 227.093,133.047
  lines w0.02: 75.089,133.053 cw(c79.089,133.053) 79.089,137.053 ; 75.09,32.058 ccw(c79.09,32.058) 79.09,28.058 ; 223.092,137.048 cw(c223.092,133.048) 227.092,133.048 ; 223.093,28.053 ccw(c223.093,32.053) 227.093,32.053

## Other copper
Top Layer:
  region net GND: 86.617,69.146 86.617,66.454 86.079,66.454 86.055,66.43 86.055,69.164
  region net GND: 130.96,39.685 130.155,38.88 130.705,38.329 130.912,38.329 131.468,38.885 131.468,39.794
  region net GND: 129.659,39.849 128.619,38.809 128.398,39.03 128.398,39.57 128.878,40.049 129.505,40.049
  region net VIN: 154.305,36.678 155.042,35.941 155.042,35.509 152.222,32.69 116.405,32.69 112.255,36.84 112.245,36.83 106.731,36.83 106.578,36.678 106.578,36.246 106.832,35.992 110.363,35.992 116.281,30.074 153.746,30.074 157.099,33.426 157.099,35.357 158.217,36.474 158.217,36.805
  region net +3.3V: 114.681,88.722 114.91,88.494 116.891,88.494 117.043,88.646 117.043,98.095 117.526,98.577 126.848,98.577 161.442,63.983 162.408,63.983 162.408,67.793 161.845,67.793 128.182,101.473 116.484,101.473 114.681,99.67
  region net NetC7_2: 107.951,37.101 106.65,37.101 106.064,37.687 106.064,40.08 107.132,41.148 107.175,41.148 107.175,43.688 107.429,43.942 109.461,43.942 109.715,43.688 109.715,41.148 108.088,39.521 108.088,37.238
  region net +3.8V: 100.546,60.046 100.546,57.988 100.749,57.785 101.358,57.785 101.485,57.912 101.485,60.021 101.335,60.171 100.673,60.173
  region net +3.8V: 98.629,68.885 98.514,68.769 98.514,65.1 98.514,64.872 98.971,64.414 99.504,64.414 99.885,64.795 99.885,68.491 99.491,68.885
  region net +3.8V: 104.748,41.489 104.102,40.843 79.667,40.843 76.289,44.221 76.289,58.877 78.325,60.914 83.701,60.914 84.417,60.198 84.417,57.226 84.29,57.099 82.969,57.099 81.546,58.522 79.413,58.522 78.778,57.887 78.778,46.355 81.165,43.967 104.104,43.967 104.748,43.324
  region net VIN: 165.75,35.5 166,35.75 166,38.25 164.75,39.5 160,39.5 159.25,40.25 159.25,44.845 159.105,44.99 157.74,44.99 157.5,44.75 157.5,39.5 156.5,38.5 150.566,38.5 150.371,38.305 148.643,38.305 148.363,38.026 148.363,37.689 148.613,37.44 149.911,37.44 151.181,36.17 161.33,36.17 162,35.5
  region net USB_5V: 137.661,45.454 134.678,45.454 134.461,45.237 134.461,42.85 136.264,41.046 137.23,41.046 137.636,41.453 137.636,43.612
  pour cut-out: 229.082,37.105 193.04,37.105 193.014,37.08 193.014,127.732 229.23,127.732
  region net +3.3V: 165.673,47.523 161.823,47.523 161.341,48.006 161.341,66.954 162.712,68.326 168.377,68.326 168.554,68.148 168.554,63.906 168.25,63.602 167.132,63.602 165.964,62.433 165.964,48.031
  region net NetC1_2: 157.673,45.747 157.854,45.928 165.072,45.928 166.5,44.5 166.5,42.25 165.703,41.453 161.967,41.453 160.934,42.485 160.934,44.308 159.992,45.25 157.863,45.25 157.673,45.44
  region net +4.5V~18V: 170,37.5 167.75,37.5 167.25,37 167.25,35.25 166.209,34.209 163.979,34.209 163,33.23 163,31 163.5,30.5 165.25,30.5 167.25,32.5 169.25,32.5 170.25,33.5 170.25,37.25
  region net +5V: 141.282,44.386 141.282,42.947 141.571,42.658 141.241,42.327 139.285,42.327 139.082,42.531 139.082,43.775 139.742,44.436
  region net NetC15_2: 149.877,38.568 150.106,38.797 150.106,40.938 150.664,41.497 150.664,44.283 149.877,45.071 148.328,45.071 148.003,44.746 148.003,39.099 148.534,38.568
  region net +5V: 147.286,44.334 146.307,45.314 139.49,45.314 139.082,44.905 139.082,41.918 139.864,41.136 143.072,41.136 145.249,41.136 145.64,40.746 146.667,40.746 147.286,41.365
  region net NetF2_1: 177.527,40.931 177.527,41.388 177.019,41.896 168.586,41.896 167.443,40.753 167.443,38.975 167.901,38.518 176.41,38.518 177.553,39.661
Bottom Layer:
  region net +3.8V: 83.909,59.538 85.687,61.316 99.276,61.316 100.546,60.046 100.546,59.288 100.721,59.112 101.263,59.112 101.485,59.334 101.485,60.173 99.149,62.509 97.574,62.509 97.574,63.017 98.971,64.414 99.504,64.414 99.885,64.795 99.885,65.837 99.606,66.116 98.717,66.116 98.514,65.913 98.514,65.1 95.923,62.509 84.569,62.509 83.045,60.985 80.149,60.985 79.946,60.782 79.946,60.096 80.505,59.538
  pour cut-out: 229.082,37.054 193.04,37.054 193.014,37.029 193.014,127.732 229.23,127.732

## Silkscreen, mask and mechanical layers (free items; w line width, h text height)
Top Overlay:
  text "5GLED" at 131.166,134.124 h1.5
  text "P2" at 170.993,134.137 h1.5
  text "P1" at 176.632,134.137 h1.5
  text "POWER" at 180.746,134.124 h1.5
  text "4GLED" at 124.612,134.061 h1.5
  text "P4" at 158.547,134.061 h1.5
  text "P5" at 152.552,134.036 h1.5
  text "P3" at 164.77,134.01 h1.5
  text "GBE_0" at 138.151,133.807 h1.5
  text "GBE_1" at 144.755,133.731 h1.5
  text "HLK-RM20-KIT" at 86.335,131.953 h3
  text "MDIO" at 162.357,120.04 h1.5 r90
  text "SPI1" at 136.779,116.561 h1.5 r90
  text "SPI2" at 152.197,116.408 h1.5 r90
  text "JTAG" at 141.884,116.357 h1.5 r90
  text "OTHER" at 157.124,116.154 h1.5 r90
  text "WO_JT" at 147.269,116.027 h1.5 r90
  text "G" at 125.324,115.595 h3
  text "T" at 125.578,112.928 h3
  text "UART" at 131.674,112.827 h1.5 r90
  text "R" at 125.552,110.236 h3
  text "N5" at 96.469,108.102 h1
  text "N3" at 120.65,105.207 h1
  text "N1" at 166.354,103.693 h1
  text "N2" at 167.208,56.617 h1
  text "N4" at 120.066,55.651 h1
  text "GND" at 146.406,49.098 h1.5
  text "3.3V" at 171.755,47.727 h1.5
  text "12V" at 109.322,46.939 h1.5
  text "GND" at 120.599,46.838 h1.5
  text "GND" at 171.45,44.679 h1.5
  text "GND" at 83.134,44.12 h1.5
  text "3.8V" at 80.213,42.367 h1.5
  text "5V" at 140.894,40.284 h1.5
  text "DC : +12V 1A" at 181.381,30.378 h2
  text "V1.0" at 209.55,29.464 h3
  text "WPS" at 86.004,28.753 h1.5
  text "RESET" at 103.48,28.677 h1.5
Bottom Overlay:
  lines w0.2: 131.97,108.583 132.69,109.303 132.69,109.957 ; 137.77,108.382 137.77,110.033 ; 142.947,110.033 142.947,107.904 144.196,106.655 144.196,98.781 144.221,98.755 ; 148.082,109.906 148.082,108.407 148.158,108.331 ; 153.057,110.033 153.057,108.995 153.848,108.204
  text "SYS_WATCHDOG" at 172.771,123.469 h1.5
  text "MDIO" at 165.379,120.625 h1.5
  text "MDC" at 165.075,118.186 h1.5
  text "GND" at 126.111,115.926 h1.5
  text "UART0_TXD" at 126.644,112.827 h1.5
  text "UART0_RXD" at 126.695,110.769 h1.5
  text "GND" at 132.309,107.188 h1.5
  text "GND" at 140.868,107.188 h1.5
  text "SPI2_MISO" at 152.197,106.705 h1.5
  text "PCIE_CKP" at 159.969,106.705 h1.5
  text "PWM0" at 132.588,105.842 h1.5
  text "JTAG_JTMS" at 142.977,105.283 h1.5
  text "SPI2_CLK" at 151.689,105.156 h1.5
  text "PCIE_CKN" at 159.893,105.156 h1.5
  text "SPI1_CS" at 133.172,104.165 h1.5
  text "USB_VBUS" at 160.477,103.708 h1.5
  text "JTAG_JTDI" at 142.748,103.683 h1.5
  text "SPI2_WP" at 151.333,103.632 h1.5
  text "WF2G_LEDIO" at 161.569,102.235 h1.5
  text "SPI2_HOLD" at 151.717,102.101 h1.5
  text "SPI1_CLK" at 133.172,102.083 h1.5
  text "JTAG_JTDO" at 142.799,101.93 h1.5
  text "JTAG_JTRST_N" at 143.866,100.508 h1.5
  text "SPI1_MOSI" at 133.274,100.482 h1.5
  text "WF5G_LEDIO" at 161.185,100.484 h1.5
  text "SPI2_MOSI" at 151.613,100.432 h1.5
  text "SYSTRSTB" at 160.043,99.009 h1.5
  text "SPI1_MISO" at 133.248,98.958 h1.5
  text "SPI2_CS" at 151.098,98.676 h1.5
  text "JTAG_JTCK" at 143.002,98.654 h1.5
  text "GND" at 145.796,97.13 h1.5
  text "WO_JTDI" at 145.796,95.301 h1.5
  text "WO_JTCK" at 145.771,93.574 h1.5
  text "WO_JTMS" at 145.821,91.872 h1.5
  text "WO_JTDO" at 145.898,90.348 h1.5
  text "GPIO48" at 101.194,90.322 h1.5
  text "GPIO49" at 107.315,90.272 h1.5
  text "WO_JTRET_N" at 147.726,88.671 h1.5
  text "GPIO46" at 101.194,88.265 h1.5
  text "GPIO47" at 107.315,88.214 h1.5
  text "GPIO44" at 101.194,86.462 h1.5
  text "GPIO45" at 107.315,86.284 h1.5
  text "GPIO40" at 101.194,84.328 h1.5
  text "GPIO42" at 107.315,84.303 h1.5
  text "GPIO43" at 101.194,82.22 h1.5
  text "GPIO41" at 107.315,82.103 h1.5
  text "GPIO56" at 107.315,80.315 h1.5
  text "PCIE_PERESET_N" at 101.194,80.137 h1.5
  text "GPIO54" at 107.315,78.41 h1.5
  text "GPIO55" at 101.194,78.359 h1.5
  text "GPIO52" at 107.315,76.403 h1.5
  text "GPIO53" at 101.194,76.352 h1.5
  text "GPIO50" at 107.315,74.371 h1.5
  text "GPIO51" at 101.194,74.27 h1.5
Mechanical 1:
  lines w0.001: 75.089,32.059 75.089,133.053 ; 79.089,137.053 223.092,137.053 ; 79.09,28.053 223.093,28.053 ; 227.093,32.053 227.093,133.047
  lines w0.02: 75.089,133.053 cw(c79.089,133.053) 79.089,137.053 ; 75.09,32.058 ccw(c79.09,32.058) 79.09,28.058 ; 223.092,137.048 cw(c223.092,133.048) 227.092,133.048 ; 223.093,28.053 ccw(c223.093,32.053) 227.093,32.053

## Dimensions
223.092,137.048 to 223.087,28.053 on Top Overlay
75.089,133.053 to 227.092,133.048 on Top Overlay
